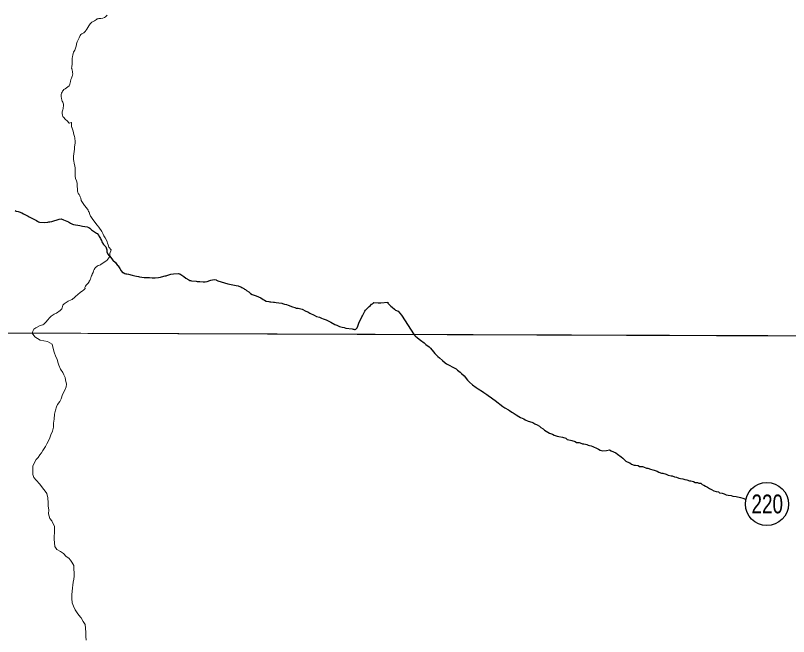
# Model space of a CAD drawing. Extents: x -1643653 to 4543381, y 1624270 to 13878484.
# Drawn here: x 592680 to 595557, y 8908816 to 8911127 of the extents above; entities that cross this region are included whole.
import ezdxf
from ezdxf.enums import TextEntityAlignment as Align

# ---------------------------------------------------------------- set-up
doc = ezdxf.new("R2010")
doc.units = 0
doc.header["$LTSCALE"] = 200
doc.layers.add('6', color=7, linetype='Continuous', lineweight=13)
doc.layers.add('60', color=7, linetype='Continuous', lineweight=13)

msp = doc.modelspace()

# ---------------------------------------------------------------- linework, layer by layer
at = {"layer": '6'}
msp.add_line((574653.9, 8910009.3), (626625.7, 8909822.1), dxfattribs=at)
for points in [[(593021, 8911127.6), (593015.2, 8911121.6), (593010.8, 8911119.1), (593005, 8911116.9), (592997.8, 8911116), (592994.4, 8911116), (592989.8, 8911115.5), (592987.6, 8911114.5), (592984.2, 8911113.6), (592980.7, 8911111.7), (592973.4, 8911106.8), (592964.4, 8911101.9), (592962.6, 8911100.6), (592957.6, 8911095.5), (592952.8, 8911088.5), (592945.7, 8911076.3), (592943.7, 8911074.8), (592942.5, 8911072.4), (592938.9, 8911066.9), (592933.7, 8911062.6), (592926.3, 8911058.4), (592923.2, 8911055.9), (592920.4, 8911052.5), (592916.1, 8911043.7), (592916.1, 8911043.7), (592909.6, 8911028.6)], [(593021, 8911127.6), (593015.2, 8911121.6), (593010.8, 8911119.1), (593005, 8911116.9), (592997.8, 8911116), (592994.4, 8911116), (592989.8, 8911115.5), (592987.6, 8911114.5), (592984.2, 8911113.6), (592980.7, 8911111.7), (592973.4, 8911106.8), (592964.4, 8911101.9), (592962.6, 8911100.6), (592957.6, 8911095.5), (592952.8, 8911088.5), (592945.7, 8911076.3), (592943.7, 8911074.8), (592942.5, 8911072.4), (592938.9, 8911066.9), (592933.7, 8911062.6), (592926.3, 8911058.4), (592923.2, 8911055.9), (592920.4, 8911052.5), (592916.1, 8911043.7), (592916.1, 8911043.7), (592909.6, 8911028.6)], [(592909.6, 8911028.6), (592908.5, 8911024.7), (592907.1, 8911020.9), (592906.4, 8911017), (592904.4, 8911009.3), (592899.9, 8910997.6), (592898, 8910993.9), (592895.4, 8910989.9), (592894.3, 8910985.6), (592892.9, 8910978.5), (592891.3, 8910974.3), (592890.1, 8910966.4), (592890.1, 8910963), (592891.2, 8910954.9), (592891, 8910946.7), (592888.9, 8910935.1), (592888.6, 8910931.1), (592889.2, 8910929.2), (592890.3, 8910922.9), (592892, 8910918.3), (592892.1, 8910914.2), (592892.6, 8910909.9), (592892.2, 8910904.3), (592891.6, 8910903.2), (592891.1, 8910901.2), (592887.7, 8910893.3), (592886, 8910888.3), (592883.8, 8910880.5), (592883, 8910875.6), (592881.9, 8910871.2), (592880.5, 8910867.1), (592879.4, 8910865.2), (592874.2, 8910861), (592864, 8910853.8), (592859.3, 8910850.9), (592858.7, 8910849.9), (592858.5, 8910848.3), (592855.2, 8910845), (592852.8, 8910840.8), (592850.9, 8910837.1), (592850.1, 8910832.8), (592850.2, 8910828.5), (592849.9, 8910824.2), (592850.6, 8910819.4), (592852.2, 8910812.2), (592853.7, 8910808.4), (592855.7, 8910804.2), (592858.1, 8910796.9), (592858.8, 8910793.1), (592857.3, 8910780.7), (592855.5, 8910775.7), (592853.5, 8910767.8), (592852.8, 8910763.4), (592852.9, 8910761.5), (592854.1, 8910755.4), (592855.6, 8910750.4), (592855.9, 8910749.9), (592858.7, 8910747.8), (592866.3, 8910739.6), (592871.8, 8910734.4), (592879.5, 8910726.3), (592880.3, 8910726.4), (592887.2, 8910728.8), (592887.9, 8910728.8), (592888, 8910711.7), (592888.2, 8910711.4), (592889.3, 8910711.1), (592894.6, 8910695.8), (592896.6, 8910683.7), (592899.7, 8910676), (592900.8, 8910672.1), (592901, 8910668.3), (592902.1, 8910660.6), (592901.9, 8910653.4), (592899.8, 8910637.4), (592899.7, 8910629.6), (592896.5, 8910611.5), (592895.3, 8910602.9), (592895.4, 8910595), (592895.3, 8910591.2), (592898.7, 8910571.6), (592900, 8910566.8), (592901.4, 8910558.8), (592901.9, 8910545.9), (592901.7, 8910528.6), (592902.9, 8910520.1), (592906.2, 8910511.7), (592908.7, 8910503.3), (592908.6, 8910499), (592909.8, 8910490.3), (592910, 8910481.9), (592910.6, 8910477.6), (592910.5, 8910473.3), (592911.1, 8910469.2), (592911.9, 8910467.9), (592912.4, 8910466.2), (592913.2, 8910465.7), (592913.5, 8910464.9), (592914.1, 8910464.3), (592914.6, 8910463), (592914.6, 8910463)], [(592909.6, 8911028.6), (592908.5, 8911024.7), (592907.1, 8911020.9), (592906.4, 8911017), (592904.4, 8911009.3), (592899.9, 8910997.6), (592898, 8910993.9), (592895.4, 8910989.9), (592894.3, 8910985.6), (592892.9, 8910978.5), (592891.3, 8910974.3), (592890.1, 8910966.4), (592890.1, 8910963), (592891.2, 8910954.9), (592891, 8910946.7), (592888.9, 8910935.1), (592888.6, 8910931.1), (592889.2, 8910929.2), (592890.3, 8910922.9), (592892, 8910918.3), (592892.1, 8910914.2), (592892.6, 8910909.9), (592892.2, 8910904.3), (592891.6, 8910903.2), (592891.1, 8910901.2), (592887.7, 8910893.3), (592886, 8910888.3), (592883.8, 8910880.5), (592883, 8910875.6), (592881.9, 8910871.2), (592880.5, 8910867.1), (592879.4, 8910865.2), (592874.2, 8910861), (592864, 8910853.8), (592859.3, 8910850.9), (592858.7, 8910849.9), (592858.5, 8910848.3), (592855.2, 8910845), (592852.8, 8910840.8), (592850.9, 8910837.1), (592850.1, 8910832.8), (592850.2, 8910828.5), (592849.9, 8910824.2), (592850.6, 8910819.4), (592852.2, 8910812.2), (592853.7, 8910808.4), (592855.7, 8910804.2), (592858.1, 8910796.9), (592858.8, 8910793.1), (592857.3, 8910780.7), (592855.5, 8910775.7), (592853.5, 8910767.8), (592852.8, 8910763.4), (592852.9, 8910761.5), (592854.1, 8910755.4), (592855.6, 8910750.4), (592855.9, 8910749.9), (592858.7, 8910747.8), (592866.3, 8910739.6), (592871.8, 8910734.4), (592879.5, 8910726.3), (592880.3, 8910726.4), (592887.2, 8910728.8), (592887.9, 8910728.8), (592888, 8910711.7), (592888.2, 8910711.4), (592889.3, 8910711.1), (592894.6, 8910695.8), (592896.6, 8910683.7), (592899.7, 8910676), (592900.8, 8910672.1), (592901, 8910668.3), (592902.1, 8910660.6), (592901.9, 8910653.4), (592899.8, 8910637.4), (592899.7, 8910629.6), (592896.5, 8910611.5), (592895.3, 8910602.9), (592895.4, 8910595), (592895.3, 8910591.2), (592898.7, 8910571.6), (592900, 8910566.8), (592901.4, 8910558.8), (592901.9, 8910545.9), (592901.7, 8910528.6), (592902.9, 8910520.1), (592906.2, 8910511.7), (592908.7, 8910503.3), (592908.6, 8910499), (592909.8, 8910490.3), (592910, 8910481.9), (592910.6, 8910477.6), (592910.5, 8910473.3), (592911.1, 8910469.2), (592911.9, 8910467.9), (592912.4, 8910466.2), (592913.2, 8910465.7), (592913.5, 8910464.9), (592914.1, 8910464.3), (592914.6, 8910463), (592914.6, 8910463)], [(592914.6, 8910463), (592915.4, 8910462.3), (592916.1, 8910460.3), (592918.7, 8910456), (592920.7, 8910451.9), (592922.6, 8910447.1), (592924.7, 8910438.7), (592926.3, 8910434.8), (592928.6, 8910430.4), (592936.2, 8910419.6), (592943.9, 8910410.6), (592949.8, 8910401.8), (592952, 8910397.9), (592953.5, 8910394.6), (592956.4, 8910386.7), (592959.2, 8910380.4), (592961.5, 8910377.9), (592961.8, 8910376.4), (592962.9, 8910374.8), (592964.8, 8910371.1), (592978.6, 8910352.2), (592983.7, 8910346.6), (592990.1, 8910338.8), (593000.6, 8910322.5), (593004.8, 8910315), (593008.5, 8910307.3), (593013.4, 8910299.5), (593019.4, 8910288), (593020.8, 8910284), (593022.5, 8910280.1), (593024.6, 8910273.2), (593027.6, 8910264.8), (593035.4, 8910254.4), (593030.7, 8910240.7), (593030.9, 8910230.2), (593020.1, 8910215.3), (592998.5, 8910201.7), (592997.4, 8910200.2), (592996.1, 8910199.2), (592992.6, 8910198.2), (592989.5, 8910197.1), (592988, 8910196.2), (592985.1, 8910195), (592981.8, 8910193.1), (592977.9, 8910188.9), (592974.2, 8910183.6), (592974, 8910182.8), (592973, 8910182.1), (592970.3, 8910177.3), (592968.2, 8910170.4), (592964.9, 8910164), (592964.4, 8910161.9), (592963.2, 8910159.9), (592962.2, 8910157.6), (592961.4, 8910154.6), (592960.4, 8910152.4), (592960.1, 8910150), (592958.9, 8910146.6), (592955.8, 8910140.3), (592954.4, 8910138.1), (592953.5, 8910135.8), (592948.4, 8910129), (592942.4, 8910123.1), (592939.8, 8910119.4), (592938, 8910115.1), (592938.7, 8910111.5), (592933.6, 8910105.6), (592931.8, 8910104.5), (592931.2, 8910103.5), (592922.2, 8910097.5), (592918.4, 8910094), (592914.6, 8910091.5), (592900.2, 8910078.7), (592890, 8910070.6), (592886.7, 8910068.4), (592875.2, 8910064.1), (592864.2, 8910056.5), (592861.2, 8910054.1), (592858.4, 8910051.3), (592856.3, 8910048.5), (592854.8, 8910044.2), (592853.8, 8910039.6), (592852, 8910035.6), (592849, 8910032.1), (592845.4, 8910028.7), (592832.4, 8910019.7), (592824.2, 8910015.7), (592815.9, 8910010.6), (592813, 8910008.1), (592806.8, 8910001.8), (592800.1, 8909994.6), (592792.6, 8909985.4), (592788.8, 8909981.5), (592784.8, 8909978), (592781.2, 8909976.4), (592771.7, 8909973.2), (592759.7, 8909967.1), (592755.4, 8909964.5), (592748.5, 8909959.2), (592745.1, 8909955.2), (592741.7, 8909944.4)], [(592914.6, 8910463), (592915.4, 8910462.3), (592916.1, 8910460.3), (592918.7, 8910456), (592920.7, 8910451.9), (592922.6, 8910447.1), (592924.7, 8910438.7), (592926.3, 8910434.8), (592928.6, 8910430.4), (592936.2, 8910419.6), (592943.9, 8910410.6), (592949.8, 8910401.8), (592952, 8910397.9), (592953.5, 8910394.6), (592956.4, 8910386.7), (592959.2, 8910380.4), (592961.5, 8910377.9), (592961.8, 8910376.4), (592962.9, 8910374.8), (592964.8, 8910371.1), (592978.6, 8910352.2), (592983.7, 8910346.6), (592990.1, 8910338.8), (593000.6, 8910322.5), (593004.8, 8910315), (593008.5, 8910307.3), (593013.4, 8910299.5), (593019.4, 8910288), (593020.8, 8910284), (593022.5, 8910280.1), (593024.6, 8910273.2), (593027.6, 8910264.8), (593035.4, 8910254.4), (593030.7, 8910240.7), (593030.9, 8910230.2), (593020.1, 8910215.3), (592998.5, 8910201.7), (592997.4, 8910200.2), (592996.1, 8910199.2), (592992.6, 8910198.2), (592989.5, 8910197.1), (592988, 8910196.2), (592985.1, 8910195), (592981.8, 8910193.1), (592977.9, 8910188.9), (592974.2, 8910183.6), (592974, 8910182.8), (592973, 8910182.1), (592970.3, 8910177.3), (592968.2, 8910170.4), (592964.9, 8910164), (592964.4, 8910161.9), (592963.2, 8910159.9), (592962.2, 8910157.6), (592961.4, 8910154.6), (592960.4, 8910152.4), (592960.1, 8910150), (592958.9, 8910146.6), (592955.8, 8910140.3), (592954.4, 8910138.1), (592953.5, 8910135.8), (592948.4, 8910129), (592942.4, 8910123.1), (592939.8, 8910119.4), (592938, 8910115.1), (592938.7, 8910111.5), (592933.6, 8910105.6), (592931.8, 8910104.5), (592931.2, 8910103.5), (592922.2, 8910097.5), (592918.4, 8910094), (592914.6, 8910091.5), (592900.2, 8910078.7), (592890, 8910070.6), (592886.7, 8910068.4), (592875.2, 8910064.1), (592864.2, 8910056.5), (592861.2, 8910054.1), (592858.4, 8910051.3), (592856.3, 8910048.5), (592854.8, 8910044.2), (592853.8, 8910039.6), (592852, 8910035.6), (592849, 8910032.1), (592845.4, 8910028.7), (592832.4, 8910019.7), (592824.2, 8910015.7), (592815.9, 8910010.6), (592813, 8910008.1), (592806.8, 8910001.8), (592800.1, 8909994.6), (592792.6, 8909985.4), (592788.8, 8909981.5), (592784.8, 8909978), (592781.2, 8909976.4), (592771.7, 8909973.2), (592759.7, 8909967.1), (592755.4, 8909964.5), (592748.5, 8909959.2), (592745.1, 8909955.2), (592741.7, 8909944.4)], [(592741.7, 8909944.4), (592752.2, 8909931.2), (592771.1, 8909918.4), (592798.7, 8909913.5), (592816.2, 8909903.9), (592820.1, 8909888.4), (592823.5, 8909874.3), (592829.9, 8909857.3), (592834.4, 8909848.3), (592837.3, 8909836.7), (592840.8, 8909826.2), (592847.7, 8909811.2), (592855.7, 8909798.1), (592859.9, 8909789.4)], [(592741.7, 8909944.4), (592752.2, 8909931.2), (592771.1, 8909918.4), (592798.7, 8909913.5), (592816.2, 8909903.9), (592820.1, 8909888.4), (592823.5, 8909874.3), (592829.9, 8909857.3), (592834.4, 8909848.3), (592837.3, 8909836.7), (592840.8, 8909826.2), (592847.7, 8909811.2), (592855.7, 8909798.1), (592859.9, 8909789.4)], [(592859.9, 8909789.4), (592864.1, 8909780.1), (592866.1, 8909770.8), (592869.2, 8909755.3), (592868.2, 8909745), (592862, 8909730.5), (592854.8, 8909716.1), (592849.2, 8909700.1), (592844.1, 8909691.1), (592836.6, 8909679.1), (592832.5, 8909670.2), (592828.5, 8909658.7), (592824.9, 8909643.7), (592823.3, 8909625.2), (592821.7, 8909610.2), (592821.2, 8909595.4)], [(592859.9, 8909789.4), (592864.1, 8909780.1), (592866.1, 8909770.8), (592869.2, 8909755.3), (592868.2, 8909745), (592862, 8909730.5), (592854.8, 8909716.1), (592849.2, 8909700.1), (592844.1, 8909691.1), (592836.6, 8909679.1), (592832.5, 8909670.2), (592828.5, 8909658.7), (592824.9, 8909643.7), (592823.3, 8909625.2), (592821.7, 8909610.2), (592821.2, 8909595.4)], [(592821.2, 8909595.4), (592817.1, 8909579.7), (592811, 8909567.2), (592807, 8909555.7), (592800.9, 8909542.2), (592796.8, 8909532.8), (592791.8, 8909523.3), (592781.2, 8909508.3), (592776.2, 8909499.8), (592770.1, 8909491.9), (592764.1, 8909482.9), (592757.1, 8909474.4), (592749.5, 8909460.9), (592744.4, 8909450.5), (592743.8, 8909435), (592743.8, 8909419.4), (592748.2, 8909407.4), (592757.2, 8909397.9), (592770.1, 8909383.3), (592780.6, 8909369.7), (592790.5, 8909357.2), (592795.7, 8909348.7)], [(592821.2, 8909595.4), (592817.1, 8909579.7), (592811, 8909567.2), (592807, 8909555.7), (592800.9, 8909542.2), (592796.8, 8909532.8), (592791.8, 8909523.3), (592781.2, 8909508.3), (592776.2, 8909499.8), (592770.1, 8909491.9), (592764.1, 8909482.9), (592757.1, 8909474.4), (592749.5, 8909460.9), (592744.4, 8909450.5), (592743.8, 8909435), (592743.8, 8909419.4), (592748.2, 8909407.4), (592757.2, 8909397.9), (592770.1, 8909383.3), (592780.6, 8909369.7), (592790.5, 8909357.2), (592795.7, 8909348.7)], [(592795.7, 8909348.7), (592800.4, 8909332.1), (592800.8, 8909314.1), (592801.7, 8909301.1), (592803.2, 8909287.1), (592803.1, 8909272.5), (592807.5, 8909255), (592815, 8909247), (592820.4, 8909235.9), (592824.4, 8909226.9), (592824.8, 8909216.4), (592824.3, 8909203.4), (592823.7, 8909188.9), (592823.7, 8909178.9), (592824.6, 8909165.3), (592826, 8909151.8), (592833, 8909139.8), (592846.9, 8909132.5)], [(592795.7, 8909348.7), (592800.4, 8909332.1), (592800.8, 8909314.1), (592801.7, 8909301.1), (592803.2, 8909287.1), (592803.1, 8909272.5), (592807.5, 8909255), (592815, 8909247), (592820.4, 8909235.9), (592824.4, 8909226.9), (592824.8, 8909216.4), (592824.3, 8909203.4), (592823.7, 8909188.9), (592823.7, 8909178.9), (592824.6, 8909165.3), (592826, 8909151.8), (592833, 8909139.8), (592846.9, 8909132.5)], [(592846.9, 8909132.5), (592858, 8909124.6), (592868, 8909114.6), (592878, 8909107.7), (592884.1, 8909100.8), (592889.3, 8909093), (592896.2, 8909079.9), (592897.2, 8909066.4), (592898.1, 8909053.4), (592898.1, 8909040.9), (592896.5, 8909029.9), (592894.4, 8909017.9), (592892.9, 8909007.9), (592891.8, 8908997.9), (592890.3, 8908983.9), (592889.7, 8908972.9), (592889.7, 8908957.4), (592891.1, 8908941.8), (592895.5, 8908929.8), (592902, 8908915.3), (592911.4, 8908900.2), (592921.8, 8908888.7), (592923.7, 8908885.4)], [(592846.9, 8909132.5), (592858, 8909124.6), (592868, 8909114.6), (592878, 8909107.7), (592884.1, 8909100.8), (592889.3, 8909093), (592896.2, 8909079.9), (592897.2, 8909066.4), (592898.1, 8909053.4), (592898.1, 8909040.9), (592896.5, 8909029.9), (592894.4, 8909017.9), (592892.9, 8909007.9), (592891.8, 8908997.9), (592890.3, 8908983.9), (592889.7, 8908972.9), (592889.7, 8908957.4), (592891.1, 8908941.8), (592895.5, 8908929.8), (592902, 8908915.3), (592911.4, 8908900.2), (592921.8, 8908888.7), (592923.7, 8908885.4)], [(592923.7, 8908885.4), (592931.3, 8908872.1), (592938.7, 8908860.6), (592940.2, 8908848), (592941.1, 8908831), (592941.5, 8908817), (592943, 8908803)], [(592923.7, 8908885.4), (592931.3, 8908872.1), (592938.7, 8908860.6), (592940.2, 8908848), (592941.1, 8908831), (592941.5, 8908817), (592943, 8908803)]]:
    msp.add_lwpolyline(points, dxfattribs=at)
at = {"layer": '6', "lineweight": 25}
for points in [[(592678.5, 8910400.8), (592682.3, 8910399.2), (592689.8, 8910397.3), (592693.7, 8910396.1), (592702.8, 8910392.2), (592709.9, 8910388.9), (592717.4, 8910384.8), (592726.8, 8910380.3), (592730.8, 8910377.9), (592757.3, 8910363.8), (592759.1, 8910362.1), (592761.8, 8910361.3), (592765.3, 8910359.5), (592769, 8910358.3), (592769.7, 8910357.8), (592788.5, 8910356.9), (592800.2, 8910357.8), (592803.8, 8910358.6), (592808, 8910359.1), (592815.2, 8910360.7), (592841.9, 8910369.3), (592849.9, 8910370.7), (592858.6, 8910366.9)], [(592858.6, 8910366.9), (592877, 8910359), (592884.1, 8910354.3), (592891.5, 8910350.2), (592895, 8910348.6), (592918.9, 8910345.6), (592929.1, 8910343.3), (592946, 8910340.7), (592953, 8910337.9), (592956.3, 8910335.7), (592956.3, 8910335.7), (592959.2, 8910333.1), (592962.7, 8910329.6), (592977, 8910319), (592980.8, 8910317.3), (592983.2, 8910315.1), (592989.3, 8910307.8), (592991.2, 8910304.8), (592993.5, 8910300.4), (592995.7, 8910297.1), (592997.5, 8910292.8), (592999.5, 8910289.4), (593001.4, 8910284.6), (593007.3, 8910274.7), (593013.5, 8910268.2), (593015.5, 8910265.5), (593017.7, 8910261.8), (593018.8, 8910258.2), (593019.4, 8910255), (593020.1, 8910247.1), (593021.9, 8910241.5), (593023.2, 8910239.3), (593027, 8910234.3), (593029.2, 8910232.3)], [(593029.2, 8910232.3), (593042, 8910216.7), (593051.5, 8910207.2), (593059.7, 8910197.1), (593061.8, 8910195), (593066, 8910188.8), (593067.7, 8910184.8), (593073.1, 8910176.6), (593078.3, 8910170.9), (593079.5, 8910170.8), (593080.4, 8910170), (593086.8, 8910167.1), (593089.9, 8910166.1), (593093.6, 8910165.5), (593100.3, 8910163.7), (593114.2, 8910160.8), (593124.2, 8910158.3), (593130.2, 8910156.4), (593137.6, 8910155.2), (593141.5, 8910154), (593158.4, 8910151.5), (593161.8, 8910151.9), (593165.2, 8910151.7), (593168.8, 8910151.9), (593175.3, 8910151.5), (593178.8, 8910151.7), (593188.9, 8910150.8), (593199.2, 8910150.7), (593212.4, 8910151.7), (593219.5, 8910153.5), (593223.2, 8910154.3), (593236.8, 8910158.1), (593240.2, 8910158.7), (593243.5, 8910159.9), (593247.3, 8910160.7), (593253.9, 8910163), (593257.3, 8910163.8), (593267.5, 8910165.5), (593284.9, 8910166.4), (593288.4, 8910166), (593291.5, 8910165)], [(593291.5, 8910165), (593294.8, 8910163.5), (593298.4, 8910160.7), (593298.4, 8910160.7), (593305.9, 8910155.4), (593313.1, 8910149.6), (593324.6, 8910142.8), (593328, 8910141.3), (593331.4, 8910140.8), (593335, 8910140), (593351.7, 8910138.3), (593355.8, 8910137.4), (593365.5, 8910137), (593378.8, 8910135.9), (593385.6, 8910136.1), (593393.1, 8910137.5), (593402.7, 8910140.5), (593406.4, 8910142.1), (593412.9, 8910143.3), (593420.1, 8910144), (593426.7, 8910143.4), (593427.9, 8910142.5), (593433.2, 8910140.1), (593470, 8910128.8), (593494.4, 8910123.5), (593501, 8910121.7), (593508.3, 8910120.7), (593511.2, 8910119.9), (593514.7, 8910118.5), (593518.2, 8910117.3), (593522.5, 8910115.2), (593529.6, 8910111), (593532.6, 8910108.9), (593536.4, 8910106.9), (593540, 8910104.1), (593547.8, 8910098.9), (593554.7, 8910093)], [(593554.7, 8910093), (593561.1, 8910088.9), (593575.2, 8910083.7), (593593.1, 8910076.1), (593601.3, 8910070.4), (593606.6, 8910067.2), (593612.7, 8910063.9), (593622.6, 8910062.1), (593626.3, 8910061.8), (593629.6, 8910061.2), (593640, 8910060.7), (593643.5, 8910059.9), (593650.2, 8910059.4), (593660.1, 8910058.2), (593670.6, 8910056), (593673.9, 8910055.6), (593680.7, 8910053.3), (593687.8, 8910051.7), (593694.5, 8910049.6), (593711.2, 8910043.1), (593719.9, 8910040.3), (593721.8, 8910039.2), (593724.7, 8910038.3), (593732, 8910037.7), (593742.2, 8910035.3), (593746.6, 8910033.6), (593761, 8910026.2), (593767.3, 8910023.6), (593775.5, 8910019.8), (593791.3, 8910011.7), (593800.5, 8910007.3), (593810.8, 8910004.2), (593819.1, 8910001), (593825.5, 8909998), (593835.5, 8909994), (593853, 8909985.5), (593867.8, 8909977.5), (593872, 8909976.1), (593875.5, 8909974.1), (593885.1, 8909970.1), (593895.5, 8909967.6), (593902.5, 8909965.3), (593909.1, 8909963.8), (593932.8, 8909961), (593936.4, 8909960), (593939.1, 8909959.7), (593941.1, 8909958.7), (593943.7, 8909958.9), (593946.2, 8909959.5), (593948.1, 8909960.9), (593951.3, 8909964.8), (593954, 8909971.3), (593957.5, 8909981.8), (593969.1, 8910005.1), (593970.9, 8910009.4), (593979.7, 8910026.9), (593982.4, 8910030.4), (593988.7, 8910036.9), (593993.8, 8910041.2), (593996.3, 8910044), (594000.9, 8910048.2), (594004.6, 8910052.2), (594005.8, 8910052.6), (594007.4, 8910054.3), (594010.6, 8910056.6)], [(594010.6, 8910056.6), (594013.9, 8910058.9), (594030.2, 8910058), (594039.3, 8910057.8), (594065.1, 8910059.8)], [(594065.1, 8910059.8), (594065.3, 8910056.9), (594071.5, 8910049.8), (594076.6, 8910045.4), (594082, 8910041.4), (594090.9, 8910033.6), (594094.4, 8910030.9), (594104.6, 8910026.1), (594117, 8910011.3), (594163.5, 8909939)], [(594163.5, 8909939), (594167.3, 8909934.5), (594175.7, 8909928), (594187.2, 8909918.9), (594200.6, 8909908.3), (594207.6, 8909903.2), (594220, 8909894.1), (594224.9, 8909888.6), (594235.3, 8909875), (594240.8, 8909869.4), (594251.7, 8909858.4), (594257.7, 8909853.3), (594268.6, 8909842.7), (594279.1, 8909834.7), (594284, 8909831.1), (594296.5, 8909824), (594304.5, 8909820), (594319.4, 8909811.8), (594324.9, 8909807.3), (594335.3, 8909799.2), (594340.3, 8909795.2), (594350.2, 8909785.6)], [(594350.2, 8909785.6), (594361.6, 8909770.5), (594369.1, 8909762.9), (594381, 8909752.9), (594393.9, 8909742.8), (594402.4, 8909737.7), (594417.8, 8909728.1), (594422.8, 8909724), (594433.7, 8909717), (594439.7, 8909712.9), (594451.2, 8909704.8), (594456.1, 8909700.8), (594465.6, 8909694.2), (594476, 8909686.1), (594482, 8909681.1), (594493.9, 8909672.5), (594500.9, 8909667.4), (594514.3, 8909659.8), (594518.8, 8909656.8), (594526.8, 8909651.2), (594532.2, 8909648.2), (594543.7, 8909641.1), (594553.7, 8909634.6), (594559.6, 8909631.5), (594571.6, 8909625.9), (594576.6, 8909622.9), (594587.5, 8909617.8), (594593, 8909616.8), (594605.5, 8909612.2), (594612.5, 8909607.1), (594622, 8909603.6), (594630.4, 8909598.5), (594635.4, 8909593.4), (594643.8, 8909589.4), (594649.3, 8909584.3), (594661.8, 8909576.2), (594667.2, 8909573.2), (594678.7, 8909569.6), (594684.2, 8909565.6), (594695.7, 8909561.5), (594702.7, 8909561), (594715.6, 8909557.9), (594727.6, 8909553.8), (594733.6, 8909549.7), (594745.1, 8909546.2), (594751.1, 8909546.1), (594763, 8909541.5), (594768.5, 8909538.5), (594777.5, 8909537.9), (594782, 8909536.4), (594790, 8909533.3), (594795.5, 8909532.8), (594801.5, 8909531.3), (594806, 8909530.7), (594811.5, 8909527.7), (594816.5, 8909527.2), (594822.4, 8909525.1), (594828.9, 8909523.1), (594833.9, 8909521), (594840.4, 8909518.5), (594844.9, 8909515.5), (594850.4, 8909513.4), (594855.8, 8909509.4), (594861.3, 8909508.8), (594865.8, 8909506.8), (594879.8, 8909508.2)], [(594879.8, 8909508.2), (594890.9, 8909511.2), (594897.3, 8909507.1), (594913.8, 8909499.5), (594920.8, 8909494.9), (594934.7, 8909484.8), (594940.7, 8909479.3), (594952.1, 8909468.7), (594957.1, 8909465.7), (594966.5, 8909462.1), (594972.5, 8909457.5), (594982.5, 8909454), (594987.5, 8909453.9), (594997, 8909452.4), (595003, 8909449.3), (595013.4, 8909448.8), (595017.9, 8909447.2), (595027.9, 8909443.2), (595033.4, 8909442.6), (595043.4, 8909439.5), (595052.4, 8909436.5), (595057.4, 8909435.4), (595068.3, 8909430.9), (595073.8, 8909427.8), (595084.3, 8909424.2), (595089.3, 8909424.2), (595101.8, 8909420.6), (595108.8, 8909417.1), (595119.7, 8909414), (595124.2, 8909414), (595133.2, 8909410.9), (595140.2, 8909409.4), (595148.2, 8909405.3), (595155.2, 8909404.2), (595163.2, 8909402.7), (595171.2, 8909400.1), (595179.1, 8909398.6), (595188.1, 8909395.5), (595193.1, 8909395), (595203.6, 8909393.4), (595210.1, 8909389.9), (595218.1, 8909388.8), (595223.6, 8909387.3), (595230.1, 8909386.2), (595235.5, 8909382.2), (595241.5, 8909379.2), (595248, 8909375.6), (595255, 8909372.1), (595262.9, 8909367), (595270.9, 8909362.9), (595278.9, 8909358.9), (595287.8, 8909355.3), (595296.3, 8909354.2), (595300.8, 8909350.7), (595310.3, 8909350.2), (595317.3, 8909346.6), (595324.8, 8909343.1), (595332.8, 8909342), (595343.3, 8909340.4), (595349.8, 8909338.9), (595362.2, 8909337.3), (595366.7, 8909335.8), (595373.2, 8909334.7), (595378.2, 8909333.2), (595386.7, 8909331.6), (595397.5, 8909327.7)]]:
    msp.add_lwpolyline(points, dxfattribs=at)
at = {"layer": '6'}
msp.add_lwpolyline([(596575.8, 8909932.4), (585614.8, 8909969.8), (585583.8, 8898914.4), (596544.8, 8898874.9)], close=True, dxfattribs=at)
at = {"layer": '6', "lineweight": 25}
msp.add_circle((595476.7, 8909309.2), 80.3, dxfattribs=at)
at = {"layer": '60', "lineweight": 25}
msp.add_spline([(814781, 9009175.5), (814787.2, 9009173.4), (814796.9, 9009173.4), (814799.4, 9009172.4), (814805.1, 9009174.5), (814805.6, 9009176.5), (814811.7, 9009179.5), (814811.7, 9009179.5), (814801.5, 9009181), (814790.7, 9009181.5), (814784.1, 9009183.1), (814777.4, 9009185.1), (814778.4, 9009175.5)], degree=3, dxfattribs=at)

# ---------------------------------------------------------------- texts
at = {"layer": '6', "width": 0.75}
msp.add_text('220', height=70, dxfattribs=at).set_placement((595478, 8909274.6), align=Align.CENTER)

doc.saveas('drawing.dxf')
